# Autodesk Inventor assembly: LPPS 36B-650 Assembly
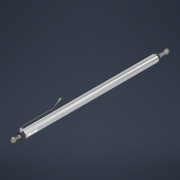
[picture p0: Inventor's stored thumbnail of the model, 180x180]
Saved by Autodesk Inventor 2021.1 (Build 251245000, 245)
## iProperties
Created: 2020-09
Part Number: LPPS 36B-650 Assembly
Document SubType Name: Assembly
Designer: J. Nielson
Author: J. Nielson
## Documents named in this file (3)
- C:\Users\Justin\Documents\CAD\The Sensor Connection\LPPS\LPPS-36B Series\3D\LPPS-36B-650\LPPS 36B-650 Assembly.iam
- C:\Users\Justin\Documents\CAD\The Sensor Connection\LPPS\LPPS-36B Series\3D\LPPS-36B-650\LPPS 36B-650 Shaft_Shrinkwrap.ipt
- C:\Users\Justin\Documents\CAD\The Sensor Connection\LPPS\LPPS-36B Series\3D\LPPS-36B-650\LPPS 36B-650_Shrinkwrap.ipt
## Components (2 placed, 2 different names)
1. LPPS 36B-650 Shaft_Shrinkwrap:1 — Mate:1, Mate:2, Cylindrical:1
2. LPPS 36B-650_Shrinkwrap:1 — Mate:1, Mate:2, Cylindrical:1
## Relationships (3: Mate 2, CylindricalJoint 1)
- Mate:1: LPPS 36B-650 Shaft_Shrinkwrap:1 ↔ LPPS 36B-650_Shrinkwrap:1
- Mate:2: LPPS 36B-650 Shaft_Shrinkwrap:1 ↔ LPPS 36B-650_Shrinkwrap:1
- Cylindrical:1: LPPS 36B-650 Shaft_Shrinkwrap:1 ↔ LPPS 36B-650_Shrinkwrap:1
